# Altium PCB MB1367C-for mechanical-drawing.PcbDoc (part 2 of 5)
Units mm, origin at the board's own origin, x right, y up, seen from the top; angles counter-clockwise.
Board outline 70 x 82.5 mm, 4 copper layers (Top Layer, Signal Layer 1, Signal Layer 2, Bottom Layer), stack 1.614 mm thick; 191 components, 143 nets, 808 pads, 920 vias.
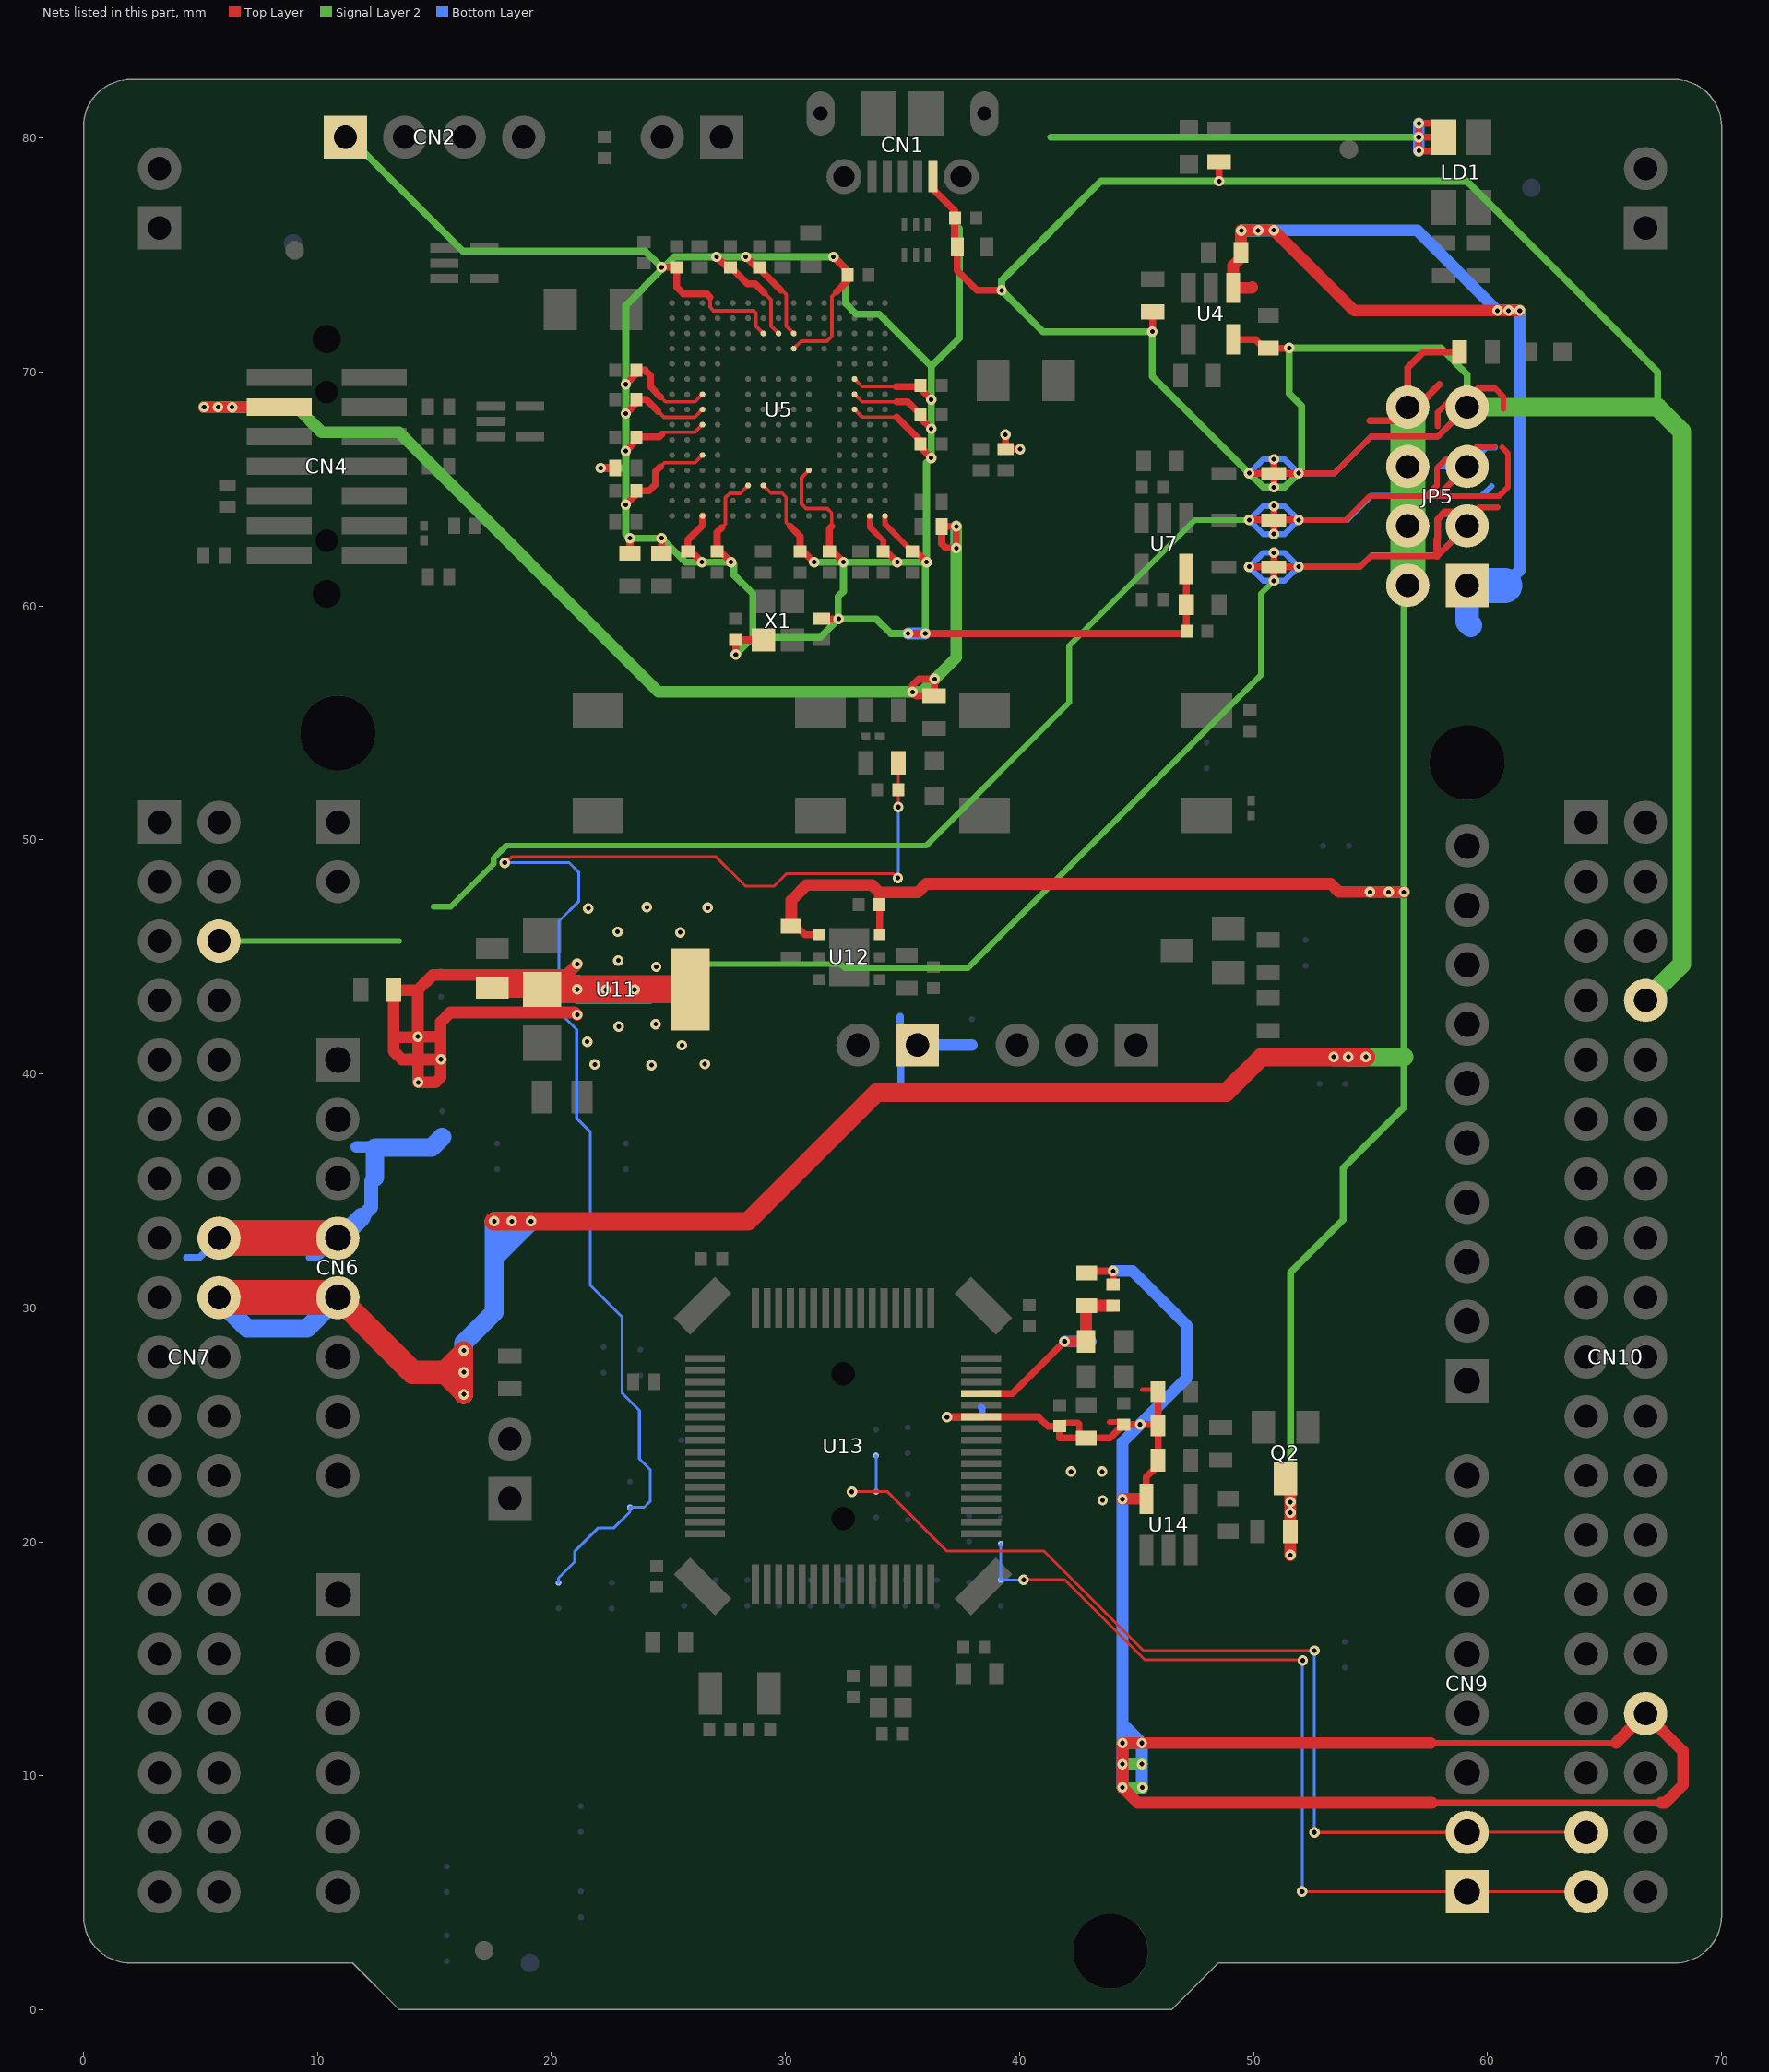
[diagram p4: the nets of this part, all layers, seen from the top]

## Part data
B1: library part MCD-00002, "Non-Open Push-Button 0.1A 24V", Manufacturer=WEALTHMETAL, Manufacturer_Part_Number=TD0341X-G01-BLU
B2: library part MCD-00001, "Non-Open Push-Button 0.1A 24V", Manufacturer=WEALTHMETAL, Manufacturer_Part_Number=TD0341X-G01-BLA
C1 C6 C7 C8 C9 C13 C14 C15 C16 C17 C18 C20 C21 C22 C23 C24 C25 C26 C27 C32 C33 C34 C35 C36 C40 C42 C44 C45 C47 C49 C52 C54: library part MCD-00102, "Capacitor, MLCC, 100nF, 16V, X7R, 10%, 0402, T=0,5mm", Manufacturer=YAGEO, Manufacturer_Part_Number=CC0402KRX7R7BB104, Package=C0402
C2: library part MCD-00205, "Capacitor, MLCC, 100pF, 50V, NPO, 5%, 0402, T=0,5mm", Manufacturer=YAGEO, Manufacturer_Part_Number=CC0402JRNPO9BN101, Package=C0402
C3: library part MCD-00016, "Capacitor, MLCC, 20pF, 50V, NPO, 5%, 0402, T=0,5mm", Manufacturer=YAGEO, Manufacturer_Part_Number=CC0402JRNPO9BN200, Package=C0402
C4: library part MCD-00012, "Capacitor, MLCC, 2.2uF, 10V, X5R, 10%, 0603, T=0,8mm", Alternate_Manufacturer=KEMET, Alternate_Manufacturer_Part_Number=C0603C225K8PACTU, Manufacturer=YAGEO, Manufacturer_Part_Number=CC0603KRX5R6BB225, Package=C0603
C5 C11 C19 C29 C31 C37 C39 C43 C48 C53: library part MCD-00010, "Capacitor, MLCC, 1uF, 16V, X5R, 10%, 0603, T=0,8mm", Manufacturer=YAGEO, Manufacturer_Part_Number=CC0603KRX5R7BB105, Package=C0603
C10 C12: library part MCD-00008, "Capacitor, MLCC, 2.2uF, 16V, X7R, 10%, 1206, T=1,15mm", Alternate_Manufacturer=KEMET, Alternate_Manufacturer_Part_Number=C1206C225K4RAC, Manufacturer=YAGEO, Manufacturer_Part_Number=CC1206KKX7R7BB225, Package=C1206
C28 C55: library part MCD-00009, "Capacitor, MLCC, 4.7uF, 16V, X5R, 10%, 0603, T=0.8mm", Manufacturer=YAGEO, Manufacturer_Part_Number=CC0603KRX5R7BB475, Package=C0603
C30: library part MCD-00011, "Capacitor, MLCC, 10nF, 16V, X7R, 10%, 0402, T=0.5mm", Manufacturer=YAGEO, Manufacturer_Part_Number=CC0402KRX7R7BB103, Package=C0402
C38 C41: library part MCD-00014, "Capacitor, MLCC, 10uF, 25V, X5R, 10%, 0805, T=0,85mm", Manufacturer=YAGEO, Manufacturer_Part_Number=CC0805KRX5R8BB106, Package=C0805
C46: library part MCD-01124, "Capacitor, MLCC, 10µF, 10V, X5R, 10%, 0603, T=0.8mm", Manufacturer=MURATA, Manufacturer_Part_Number=GRM188R61A106KAAL, Package=C0603
C50: library part MCD-00211, "Capacitor, MLCC, 100nF, 16V, X7R, 10%, 0603, T=0,8mm", Manufacturer=YAGEO, Manufacturer_Part_Number=CC0603KRX7R7BB104, Package=C0603
C51: library part MCD-01101, "Capacitor,100pF,50V,X7R,10%,0603", Manufacturer=AVX, Manufacturer_Part_Number=06035C101JAT4A, Package=C0603
C56 C59: library part MCD-00674, "Capacitor, MLCC, 6.8pF, 50V, NPO, +-0.25pF, 0402, T=0.5mm", Manufacturer=YAGEO, Manufacturer_Part_Number=CC0402CRNPO9BN6R8, Package=C0402
C57 C58: library part MCD-00003, "Capacitor, MLCC, 5.1pF, 50V, NPO, +-0.25pF, 0402, T=0.5mm", Manufacturer=YAGEO, Manufacturer_Part_Number=CC0402CRNPO9BN5R1, Package=C0402
CN1: library part MCD-00028, "USB-MICRO-B, 0.65mm, RA, SMT, Bottom Mount,", Manufacturer=MOLEX, Manufacturer_Part_Number=1050170001
CN2: library part MCD-00029, "Header, 4x1, 2,54mm, VR, TH, Height 5.84mm/2.54mm", Manufacturer=SAMTEC, Manufacturer_Part_Number=TSW-104-07-x-S
CN4: library part MCD-00592, "Header 7x2, 1.27mm, Dual row, Straight, \"STDC14_MEDIUM\" : footprint compatible with FTSH-107-01-L-DV,-K,-A,-P,-ES (use \"STDC14_BIG\" to also be compatible with SHF-107-01-L-D-SM,-K)", Manufacturer=SAMTEC, Manufacturer_Part_Number=FTSH-107-01-L-DV-K
CN5: library part MCD-00262, "Socket, 10x1, 2.54mm, VR, TH, Height 8.51mm/10mm", Manufacturer=SAMTEC, Manufacturer_Part_Number=SSW-110-03-x-S
CN6 CN9: library part MCD-00261, "Socket, 8x1, 2.54mm, VR, TH, Height 8.51mm/10mm", Manufacturer=SAMTEC, Manufacturer_Part_Number=SSW-108-03-x-S
CN7 CN10: library part MCD-00213, "Header, 19x2, 2,54mm, VR, TH, Height 5.84mm/10.16mm", Manufacturer=SAMTEC, Manufacturer_Part_Number=TSW-119-09-x-D
CN8: library part MCD-00260, "Socket, 6x1, 2.54mm, VR, TH, Height 8.51mm/10mm", Manufacturer=SAMTEC, Manufacturer_Part_Number=SSW-106-03-x-S
CN11 CN12: library part MCD-00214, "Header, 2x1, 2,54mm, VR, TH, Height 5.84mm/10.16mm", Manufacturer=SAMTEC, Manufacturer_Part_Number=TSW-102-09-x-S
D1 D2 D3: library part MCD-00034, "BAT60JFILM", Manufacturer=STMICROELECTRONICS
HW104: library part MCD-00626, "\"CE\" logo footprint for PCB"
HW106: library part MCD-00625, "\"STMicroelectronics\" logo footprint for PCB", Manufacturer=n/a
HW107: library part MCD-00627, "\"Hand\" ESD logo footprint for PCB", Manufacturer=n/a
JP1 JP7: library part MCD-00045, "Header, 2x1, 2,54mm, VR, TH, Height 5.84mm/2.54mm", Manufacturer=SAMTEC, Manufacturer_Part_Number=TSW-102-07-x-S
JP3 JP6: library part MCD-00683, "Header, 2x1, 2,54mm, VR, TH, Height 5.84mm/2.54mm - Shunt Fitted by default", Manufacturer=SAMTEC, Manufacturer_Part_Number=TSW-102-07-x-S
JP5: library part MCD-00686, "Header, 4x2, 2,54mm, VR, TH, Height 5.84mm/2.54mm - Shunt Fitted 1-2", Manufacturer=SAMTEC, Manufacturer_Part_Number=TSW-104-07-x-D
JP8: library part MCD-00684, "Header, 3x1, 2,54mm, VR, TH, Height 5.84mm/2.54mm - Shunt Fitted 1-2 by default", Manufacturer=SAMTEC, Manufacturer_Part_Number=TSW-103-07-F-S
L1 L2: library part MCD-00047, "SMD Chip ferrite bead, 600R@100MHz +/-25%, 350mA, 500mohm DC, 0603, T=0.8mm", Manufacturer=TAI-TECH, Manufacturer_Part_Number=FCM1608KF-601T03
LD1: library part MCD-00051, "LED Bicolor", Alternate_Manufacturer=EVERLUCK, Alternate_Manufacturer_Part_Number=LE-RGW35280, Manufacturer="AVAGO TECHNOLOGIES", Manufacturer_Part_Number=HSMF-A201-A00J1
LD2 LD3: library part MCD-00050, "LED, Green, 0603", Manufacturer=EVERLIGHT, Manufacturer_Part_Number=19-213SYGC/S530-E2/TR8, Package="LED 0603"
LD4: library part MCD-00049, "LED, Red, 0603", Manufacturer=EVERLIGHT, Manufacturer_Part_Number=19-213-R6C-AP1Q2B/3T, Package="LED 0603"
Q1 Q2: library part MCD-00073, "NPN Bipolar Transistor", Manufacturer=NXP, Manufacturer_Part_Number=BSR14
R1 R30: library part MCD-00070, "Resistor,1K,0603,1%,1/10W", Manufacturer=YAGEO, Manufacturer_Part_Number=RC0603FR-071KL, Package=R0603
R2 R3 R27: library part MCD-00197, "Resistor,330R,0603,1%,1/10W", Manufacturer=YAGEO, Manufacturer_Part_Number=RC0603FR-07330RL, Package=R0603
R4 R15 R20: library part MCD-00119, "Resistor,100R,0402,1%,1/16W", Manufacturer=YAGEO, Manufacturer_Part_Number=RC0402FR-07100RL, Package=R0402
R5: library part MCD-00185, "Resistor,3K,0402,1%,1/16W", Manufacturer=YAGEO, Manufacturer_Part_Number=RC0402FR-073KL, Package=R0402
R6 R26 R28: library part MCD-00223, "Resistor,100K,0603,1%,1/10W", Manufacturer=YAGEO, Manufacturer_Part_Number=RC0603FR-07100KL, Package=R0603
R7 R25: library part MCD-00225, "Resistor,510R,0603,1%,1/10W", Manufacturer=YAGEO, Manufacturer_Part_Number=RC0603FR-07510RL, Package=R0603
R8 R31: library part MCD-00220, "Resistor,10K,0603,1%,1/10W", Manufacturer=YAGEO, Manufacturer_Part_Number=RC0603FR-0710KL, Package=R0603
R9 R10 R13 R18 R22 R23 R32: library part MCD-00189, "Resistor,22R,0402,1%,1/16W", Manufacturer=YAGEO, Manufacturer_Part_Number=RC0402FR-0722RL, Package=R0402
R11 R16 R19: library part MCD-00065, "Resistor,4K7,0402,1%,1/16W", Alternate_Manufacturer=YAGEO, Alternate_Manufacturer_Part_Number=RT0402FRE074K7L, Manufacturer_Part_Number=RC0402FR-074K7L, Package=R0402
R12: library part MCD-00055, "Resistor,2K7,0402,1%,1/16W", Manufacturer=YAGEO, Manufacturer_Part_Number=RC0402FR-072K7L, Package=R0402
R14 R17 R21 R24: library part MCD-00053, "Resistor,10K,0402,1%,1/16W", Manufacturer=YAGEO, Manufacturer_Part_Number=RC0402FR-0710KL, Package=R0402
R29: library part MCD-00222, "Resistor,47K,0603,1%,1/10W", Manufacturer=YAGEO, Manufacturer_Part_Number=RC0603FR-0747KL, Package=R0603
R33: library part MCD-01215, "resistor, 10K, 0603, 0.5%, 1/10W", Manufacturer=YAGEO, Manufacturer_Part_Number=RC0603DR-0710KL, Package=R0603
R34: library part MCD-01209, "Resistor,33K,0603,0.5%,1/10W", Manufacturer=YAGEO, Manufacturer_Part_Number=RC0603DR-0733KL, Package=R0603
R35: library part MCD-00528, "Resistor,820R,0603,1%,1/10W", Manufacturer=YAGEO, Manufacturer_Part_Number=RC0603FR-07820RL, Package=R0603
SB1 SB2 SB3 SB4 SB5 SB6 SB7 SB8 SB9 SB10 SB11 SB12 SB13 SB14 SB15 SB16 SB17 SB18 SB19 SB20 SB21 SB22 SB23 SB24 SB25 SB26 SB27 SB28 SB29 SB30 SB31 SB32 SB33 SB34 SB35 SB36 SB37 SB38 SB39 SB40 SB41: library part MCD-00071, "Solder Bridge ON"
U1 U6: library part MCD-00136, "Dual Transil array for ESD protection", Manufacturer=STMICROELECTRONICS, Manufacturer_Part_Number=ESDALC6V1W5
U2: library part MCD-00649, "Common mode filter with ESD protection for USB 2.0 interface", Manufacturer=STMICROELECTRONICS, Manufacturer_Part_Number=ECMF02-2AMX6
U3: library part MCD-00251, "High power transient voltage suppressor, 7V breakdown", Manufacturer=STMICROELECTRONICS, Manufacturer_Part_Number=ESDA7P60-1U1M
U4: library part MCD-00159, "500mA, Enhanced single channel power switches with active high enable pin", Alternate_Manufacturer="TEXAS INSTRUMENTS", Alternate_Manufacturer_Part_Number=TPS2051C, Manufacturer=STMICROELECTRONICS, Manufacturer_Part_Number=STMPS2151STR
U5: library part MCD-00596, "STM32F723IEK  (STM32F7) BGA176", Manufacturer=STMICROELECTRONICS, Manufacturer_Part_Number=STM32F723IEK6
U7: library part MCD-00086, "Ultra low drop-low noise BiCMOS voltage, regulators low ESR capacitors compatible", Manufacturer=STMICROELECTRONICS, Manufacturer_Part_Number=LD3985M33R
U8 U9 U10: library part MCD-00170, "ESD protection 6V1", Manufacturer=STMICROELECTRONICS, Manufacturer_Part_Number=ESDALC6V1-1U2
U11: library part MCD-00088, "IC REG LDO 5V 0.8A SOT223", Manufacturer=STMICROELECTRONICS, Manufacturer_Part_Number=LD1117S50TR
U12: library part MCD-00215, "Low quiescent current and low noise voltage regulators", Manufacturer=STMICROELECTRONICS, Manufacturer_Part_Number=LD39050PU33R
U13: library part MCD-01243, "STM32G474, LQFP64 package,  3D IC footprint with 2D socket footprint.", Manufacturer=STMICROELECTRONICS, Manufacturer_Part_Number=STM32G474RET6, Package=LQFP64
U14: library part MCD-01157, "Programmable voltage reference", Manufacturer=STMICROELECTRONICS, Manufacturer_Part_Number=TL1431ACL5T, Package=SOT23-5L
X1: library part MCD-00597, "Oscillator 25.00Mhz, -+50PPM, 3.3V, Temp -55 to +125°C", Alternate_Manufacturer="AVX CORP/KYOCERA CORP", Alternate_Manufacturer_Part_Number=KC2520B25.0000C10E00, Manufacturer=NDK, Manufacturer_Part_Number="NZ2520SB 25MHz END4869B"
X2: library part MCD-00091, "Crystal 32.768kHz, 6pF, -+20PPM, R=50K, SMD", Manufacturer=NDK, Manufacturer_Part_Number="NX3215SA 32.768KHz EXS00A-MU00525"
X3: library part MCD-01036, "24MHz crystal oscillator - Cl:6pf -", Manufacturer=NDK, Manufacturer_Part_Number="NX2016SA 24MHz EXS00A-CS10820", Package="(2016) 2.0 x 1.6 x 0.45 mm"

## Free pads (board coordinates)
  round 3.2 hole 3.2 unplated: 0(10.87,54.57) 0(43.89,2.5) 0(59.13,53.3)

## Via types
v1: diameter 0.45, hole 0.2, Top Layer to Bottom Layer, tented both sides, 920 vias

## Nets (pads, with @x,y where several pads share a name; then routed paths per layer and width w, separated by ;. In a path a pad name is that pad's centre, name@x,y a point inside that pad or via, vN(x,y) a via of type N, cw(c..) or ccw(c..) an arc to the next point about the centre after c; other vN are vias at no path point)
3V3: CN4.3 CN6.4 CN7.16 JP6.1 R19.2 R25.1 SB5.2 SB39.1 | length 88.7
  Top Layer w0.3: v1(6.35,68.495) v1@6.36,68.505 ; v1(35.425,56.325) 35.585,56.165 R25.1@36.345,56.165 36.375,56.195 v1(36.375,56.875) 35.7,56.875 35.425,56.6 v1(35.425,56.325) ; 36.675,62.65 R19.2@36.675,63.4 v1(37.3,63.4) v1(37.3,62.475) 36.85,62.475 36.675,62.65
  Top Layer w0.5: v1(5.15,68.5) v1(5.75,68.5) 5.755,68.495 v1(6.35,68.495) ; v1@6.36,68.505 CN4.3@8.363,68.505
  Top Layer w1.5: CN7.16@5.79,32.98 CN6.4@10.87,32.98
  Signal Layer 2 w0.5: v1(5.15,68.5) v1(5.75,68.5) 6.345,68.5 v1(6.35,68.495) 9.105,68.495 10.175,67.425 13.475,67.425 24.575,56.325 v1(35.425,56.325) 35.825,56.325 v1(36.375,56.875) 37.3,57.8 v1(37.3,62.475) v1(37.3,63.4)
  Signal Layer 2 w1.5: CN7.16@5.79,32.98 CN6.4@10.87,32.98
  Bottom Layer w0.3: 4.4,32.15 4.96,32.15 CN7.16@5.79,32.98 ; 9.65,32.15 10.04,32.15 CN6.4@10.87,32.98 ; 34.9,42.45 34.9,41.97 JP6.1@35.635,41.235 34.925,40.525 34.925,39.625
  Bottom Layer w0.5: v1(5.15,68.5) v1(5.75,68.5) 5.753,68.498 6.347,68.498 v1(6.35,68.495) ; 11.65,36.875 12.425,36.875 12.45,36.85 ; v1(35.425,56.325) 35.825,56.325 v1(36.375,56.875) ; JP6.1@35.635,41.235 37.965,41.235 SB5.2@37.97,41.24 ; v1(37.3,62.475) v1(37.3,63.4)
  Bottom Layer w0.6: 11.875,33.875 12.3,34.3 12.3,35.425 12.45,35.575
  Bottom Layer w0.8: CN7.16@5.79,32.98 CN6.4@10.87,32.98 10.98,32.98 11.875,33.875 ; 12.45,35.575 12.45,36.85 14.3,36.85 14.875,36.85 SB39.1@15.325,37.3
3V3_STLK: C6.2 C7.2 C8.2 C9.2 C13.2 C14.2 C15.2 C16.2 C17.2 C18.2 C21.2 C22.2 C23.2 C24.2 C25.2 C26.2 C27.2 C28.2 C29.2 C31.2 C32.2 C33.2 CN2.1 LD1.4 R14.1 R24.1 U5.C1 U5.C5 U5.C7 U5.C8 U5.C9 U5.F3 U5.G3 U5.G13 U5.H13 U5.J12 U5.J13 U5.K4 U5.N8 U5.N9 U5.N10 U5.P1 U5.R1 U7.5 X1.4 | length 200.2
  Top Layer w0.15: 24.55,68.325 24.805,68.07 26.12,68.07 U5.C8@26.45,68.4 ; 24.65,65.95 24.825,66.125 26.125,66.125 U5.C5@26.45,66.45 ; 24.65,68.95 24.875,68.725 26.125,68.725 U5.C9@26.45,69.05 ; 24.725,67.35 24.805,67.43 26.13,67.43 U5.C7@26.45,67.75 ; 27.275,63.35 27.43,63.505 27.43,64.633 27.617,64.82 28.07,64.82 U5.F3@28.4,65.15 ; U5.G3@29.05,65.15 29.37,64.83 29.845,64.83 30.025,64.65 30.025,63.575 30.2,63.4 ; U5.J12@30.35,71 30.67,71.32 31.773,71.32 31.98,71.527 31.98,73.23 32.175,73.425 ; U5.K4@31,65.8 30.68,65.48 30.68,64.367 30.877,64.17 31.783,64.17 31.975,63.978 31.975,63.4 ; U5.N8@32.95,68.4 33.27,68.08 34.745,68.08 ; U5.N9@32.95,69.05 33.275,68.725 34.75,68.725 ; U5.N10@32.95,69.7 33.275,69.375 34.725,69.375
  Top Layer w0.16: 26.775,73.2 26.775,73.085 26.775,72.775 26.925,72.625 28.5,72.625 ; 28.535,72.625 28.625,72.625 28.725,72.525 28.725,72.165 28.725,71.975 U5.G13@29.05,71.65 ; 29.1,73.375 29.375,73.1 29.375,71.975 U5.H13@29.7,71.65 ; 29.825,73.5 30.025,73.3 30.025,71.975 U5.J13@30.35,71.65
  Top Layer w0.25: U5.P1@33.6,63.85 33.6,63.375 34.175,62.8 C26.2@34.175,62.325 ; U5.R1@34.25,63.85 34.25,63.5 C27.2@35.425,62.325
  Top Layer w0.3: v1(22.1,65.9) R14.1@22.725,65.9 ; v1(23.175,64.325) 23.625,64.775 C21.2@23.625,64.925 24.175,64.925 24.45,65.2 24.45,65.75 24.65,65.95 ; v1(23.175,66.625) 23.625,67.075 C17.2@23.625,67.225 24.6,67.225 24.725,67.35 ; v1(23.175,68.225) 23.625,68.675 C15.2@23.625,68.825 24.05,68.825 24.55,68.325 ; v1(23.175,69.475) C13.2@23.625,69.925 ; C28.2@23.35,62.25 v1(23.35,62.9) ; C13.2@23.675,69.925 C13.2@23.625,69.925 ; 24.65,68.95 24.225,69.375 24.225,69.85 24,70.075 C13.2@23.625,70.075 C13.2@23.625,69.925 ; C29.2@24.7,62.25 v1(24.7,62.9) ; v1(24.7,74.475) C6.2@25.35,74.475 25.35,73.625 25.625,73.35 26.625,73.35 26.775,73.2 ; v1(26.425,61.875) 25.975,62.325 C22.2@25.825,62.325 25.825,62.825 26.45,63.45 U5.C1@26.45,63.85 ; v1(27.05,74.925) 27.5,74.475 C7.2@27.65,74.475 ; 27.275,63.35 27.075,63.15 C23.2@27.075,62.325 27.225,62.325 v1(27.675,61.875) ; C7.2@27.65,74.45 27.7,74.45 28.375,73.775 28.7,73.775 29.1,73.375 ; v1(27.875,57.925) C32.2@27.875,58.55 X1.4@29.05,58.55 ; v1(28.3,74.925) 28.75,74.475 C8.2@28.9,74.475 28.9,74.4 29.8,73.5 ; 30.2,63.4 30.625,62.975 C24.2@30.625,62.325 30.775,62.325 v1(31.225,61.875) ; R24.1@31.55,59.45 v1(32.275,59.45) ; 31.975,63.4 31.875,63.3 C25.2@31.875,62.325 32.025,62.325 v1(32.475,61.875) ; v1(32.05,74.925) 32.65,74.325 C9.2@32.65,74.15 32.65,73.9 32.175,73.425 ; C26.2@34.175,62.325 34.325,62.325 v1(34.775,61.875) ; 34.725,69.375 35.725,69.375 C14.2@35.775,69.425 35.775,69.275 v1(36.225,68.825) ; 34.745,68.08 35.775,67.05 C18.2@35.775,66.925 35.775,66.775 v1(36.225,66.325) ; 34.75,68.725 35.225,68.725 C16.2@35.775,68.175 35.775,68.025 v1(36.225,67.575) ; v1(35.238,58.825) v1(35.975,58.825) 47.23,58.825 C33.2@47.13,58.925 C31.2@47.13,60.05 U7.5@47.13,61.575 ; C27.2@35.425,62.325 35.575,62.325 v1(36.025,61.875) ; v1(57.06,80.04) v1@57.065,80.04 ; LD1.4@58.12,80.04 v1@57.065,80.04 ; LD1.4@58.125,79.45 v1(57.065,79.45) v1@57.065,80.04 ; LD1.4@58.125,80.625 v1(57.065,80.625) v1@57.065,80.04
  Signal Layer 2 w0.3: CN2.1@11.19,80.04 11.335,80.04 16.2,75.175 24,75.175 v1(24.7,74.475) v1@24.7,74.375 ; v1(22.1,65.9) 23.15,65.9 23.175,65.875 ; v1(27.875,57.925) 28.6,58.65 ; v1(31.225,61.875) v1(32.475,61.875) ; 37.425,76.125 37.425,71.45 36.225,70.25 ; 41.34,80.04 v1(57.06,80.04) ; 23.175,65.875 v1(23.175,64.325) 23.175,63.075 v1(23.35,62.9) v1(24.7,62.9) 25.725,61.875 v1(26.425,61.875) v1(27.675,61.875) 27.785,61.765 27.785,61.335 28.6,60.52 28.6,58.65 ; 23.175,65.875 v1(23.175,66.625) v1(23.175,68.225) v1(23.175,69.475) 23.175,72.85 v1@24.7,74.375 ; v1@24.7,74.375 25.25,74.925 v1(27.05,74.925) v1(28.3,74.925) v1(32.05,74.925) 32.575,74.4 32.575,72.925 33.025,72.475 34,72.475 36.225,70.25 ; 28.6,58.65 31.475,58.65 v1(32.275,59.45) ; v1(32.275,59.45) 32.255,59.47 32.255,60.405 32.475,60.625 v1(32.475,61.875) ; v1(32.275,59.45) 33.875,59.45 34.5,58.825 v1(35.238,58.825) v1(35.975,58.825) 35.975,61.825 v1(36.025,61.875) ; v1(32.475,61.875) v1(34.775,61.875) v1(36.025,61.875) ; v1(36.025,61.875) 36.025,66.125 v1(36.225,66.325) v1(36.225,67.575) v1(36.225,68.825) 36.225,70.25
  Bottom Layer w0.5: v1(35.238,58.825) v1(35.975,58.825) ; v1(57.065,79.45) v1(57.065,80.625)
5V: C36.2 C37.2 CN6.5 CN7.18 JP5.2 JP5.4 JP5.6 JP5.8 Q2.3 R7.2 R12.1 R35.2 U12.1 U12.6 | length 186.8
  Top Layer w0.3: C37.2@30.245,46.315 30.46,46.315 30.835,45.94 U12.1@31.42,45.94 ; U12.6@34.02,45.94 C36.2@34.02,47.24 ; v1(39.4,67.325) R12.1@39.4,66.7 v1(40.025,66.7) ; Q2.3@51.37,22.69 Q2.3@51.57,22.49 ; v1@51.57,19.43 v1(51.575,19.435) ; 54.975,67.925 56.015,67.925 JP5.8@56.59,68.5 ; 57.95,69.475 56.975,68.5 JP5.8@56.59,68.5 ; R7.2@58.8,70.85 57.25,70.85 56.59,70.19 JP5.8@56.59,68.5
  Top Layer w0.5: C37.2@30.245,46.315 30.245,47.42 30.9,48.075 33.7,48.075 34.02,47.755 ; C36.2@34.02,47.24 34.02,47.755 ; v1@51.57,19.43 R35.2@51.57,20.44 Q2.3@51.57,22.49 ; v1(56.425,47.775) 56.425,47.75 56.4,47.775 v1(55.775,47.775) v1(54.975,47.775) 53.65,47.775 53.3,48.125 36.015,48.125 35.645,47.755 34.02,47.755
  Top Layer w0.8: v1(16.25,26.3) v1@16.25,26.325 ; v1(17.55,33.7) v1(18.3,33.7) v1(19.125,33.7) 28.4,33.7 33.9,39.2 48.825,39.2 50.35,40.725 v1(53.425,40.725) v1(54.05,40.725) v1(54.8,40.725) ; 15.325,27.25 v1(16.25,28.175) v1(16.25,27.25) ; 15.325,27.25 v1(16.25,27.25) ; 15.325,27.25 v1@16.25,26.325 ; v1@16.25,26.325 v1(16.25,27.25)
  Top Layer w1: CN6.5@10.87,30.44 14.06,27.25 15.325,27.25
  Top Layer w1.5: CN7.18@5.79,30.44 CN6.5@10.87,30.44
  Signal Layer 2 w0.3: v1(51.575,19.435) v1(51.575,21.25) v1(51.575,21.7) 51.575,31.525 53.825,33.775 53.825,35.975 56.425,38.575 56.425,40.725 v1(56.425,47.775) 56.425,60.715 JP5.2@56.59,60.88
  Signal Layer 2 w0.5: v1(55.775,47.775) v1(56.425,47.775)
  Signal Layer 2 w0.8: v1(16.25,26.3) v1(16.25,27.25) v1(16.25,28.175) ; v1(17.55,33.7) v1(18.3,33.7) v1(19.125,33.7) ; v1(54.05,40.725) v1(54.8,40.725) 56.425,40.725
  Signal Layer 2 w1.5: CN7.18@5.79,30.44 CN6.5@10.87,30.44 ; JP5.2@56.59,60.88 JP5.4@56.59,63.42 JP5.6@56.59,65.96 JP5.8@56.59,68.5
  Bottom Layer w0.3: v1(51.575,19.435) v1(51.575,21.25) v1@51.575,21.675
  Bottom Layer w0.5: v1(54.975,47.775) v1(55.775,47.775) v1(56.425,47.775)
  Bottom Layer w0.8: CN7.18@5.79,30.44 5.79,30.335 7,29.125 9.555,29.125 CN6.5@10.87,30.44 ; v1(16.25,26.3) v1(16.25,27.25) v1(16.25,28.175) 16.25,28.5 17.55,29.8 17.55,32.125 ; v1(53.425,40.725) v1(54.05,40.725) v1(54.8,40.725) ; 17.55,32.125 17.55,32.95 ; 17.55,32.125 v1(19.125,33.7) v1(18.3,33.7) ; 17.55,32.95 v1(17.55,33.7) v1(18.3,33.7) ; 17.55,32.95 v1(18.3,33.7)
5V_USB_CHGR: C2.2 C11.2 CN1.1 CN10.8 D1.1 JP5.7 R1.2 R6.2 U3.1 U4.5 | length 143.8
  Top Layer w0.25: v1(51.925,65.675) 53.45,65.675 55.025,67.25 57.88,67.25 JP5.7@59.13,68.5 ; 57.875,67.675 57.875,68.275 58.475,68.875 58.755,68.875 JP5.7@59.13,68.5 ; 60.675,68.425 60.675,68.95 60.325,69.3 59.575,69.3 59.13,68.855 JP5.7@59.13,68.5
  Top Layer w0.3: CN1.1@36.3,78.35 36.3,77.82 37.18,76.94 ; v1(39.235,73.49) 39.235,73.553 39.172,73.49 38.185,73.49 37.33,74.345 37.33,75.64 37.215,75.64 37.225,75.65 C2.2@37.225,76.845 ; v1(45.675,71.725) 45.685,71.735 R6.2@45.685,72.57 ; v1(48.533,78.158) R1.2@48.533,78.98 ; U4.5@49.125,71.395 50.08,71.395 50.455,71.02 C11.2@50.635,71.02 51.52,71.02 v1(51.525,71.025) ; v1(49.815,65.675) D1.1@50.87,65.675 ; v1(50.87,65.075) D1.1@50.87,65.675 ; v1(50.87,66.275) D1.1@50.87,65.675 ; v1(51.925,65.675) D1.1@50.87,65.675 ; 37.18,76.94 37.18,76.89 C2.2@37.225,76.845 ; 37.18,76.94 37.225,76.895 C2.2@37.225,76.845
  Signal Layer 2 w0.3: JP5.7@59.13,68.5 59.13,69.895 58,71.025 v1(51.525,71.025) 51.525,69.075 52.05,68.55 52.05,65.8 v1(51.925,65.675) 51.325,65.075 v1(50.87,65.075) 50.415,65.075 v1(49.815,65.675) 45.675,69.815 v1(45.675,71.725) 41,71.725 v1(39.235,73.49) 39.235,73.91 43.483,78.158 v1(48.533,78.158) 59.117,78.158 67.275,70 67.275,68.5
  Signal Layer 2 w0.8: JP5.7@59.13,68.5 67.275,68.5 68.3,67.475 68.3,44.69 CN10.8@66.75,43.14
  Bottom Layer w0.25: JP5.7@59.13,68.5 57.88,67.25 55.025,67.25 53.45,65.675 v1(51.925,65.675) ; v1(51.925,65.675) 51.325,66.275 v1(50.87,66.275) 50.415,66.275 v1(49.815,65.675) 50.415,65.075 v1(50.87,65.075) 51.325,65.075 v1(51.925,65.675)
5V_USB_STLK: C5.2 JP5.1 U4.1 | length 47.8
  Top Layer w0.3: C5.2@49.46,74.885 C5.2@49.46,75.12
  Top Layer w0.5: C5.2@49.46,74.885 49.125,74.55 U4.1@49.125,73.595 49.92,73.595 49.95,73.625 ; C5.2@49.46,75.12 49.46,76.06 v1(50.865,76.06) 54.3,72.625 v1(60.425,72.625) v1(60.9,72.625) v1(61.375,72.625)
  Signal Layer 2 w0.5: v1(49.475,76.045) 49.48,76.05 v1(50.2,76.05) 50.21,76.06 v1(50.865,76.06) ; v1(60.425,72.625) v1(60.9,72.625) v1(61.375,72.625)
  Bottom Layer w0.5: v1(49.475,76.045) 50.195,76.045 v1(50.2,76.05) 50.855,76.05 v1(50.865,76.06) 56.99,76.06 v1(60.425,72.625) v1(60.9,72.625) v1(61.375,72.625) 61.375,61.525 60.73,60.88
  Bottom Layer w1: JP5.1@59.13,60.88 59.13,59.32 59.275,59.175
  Bottom Layer w1.5: JP5.1@59.13,60.88 60.73,60.88
5V_VIN: C38.2 D3.1 JP5.3 R30.2 U11.2 U11.4 | length 107.8
  Top Layer w0.25: v1(51.925,61.675) 54.55,61.675 55.005,62.13 57.84,62.13 JP5.3@59.13,63.42 59.13,63.73 59.616,64.216 60.416,64.216 60.425,64.225
  Top Layer w0.3: v1(49.815,61.675) D3.1@50.87,61.675 ; v1(50.87,61.075) D3.1@50.87,61.675 ; v1(50.87,62.275) D3.1@50.87,61.675 ; v1(51.925,61.675) D3.1@50.87,61.675 ; 57.84,62.13 57.84,62.842 57.865,62.867 57.865,63.703 58.17,64.008 58.542,64.008 JP5.3@59.13,63.42
  Top Layer w0.5: v1(15.275,40.625) v1@15.265,40.615 ; v1(21.1,42.525) 21,42.625 15.675,42.625 15.265,42.215 15.265,41.575 ; v1(21.1,44.7) 20.625,44.225 14.925,44.225 14.285,43.585 ; 13.25,41.575 14.265,41.575 v1(14.285,41.595) ; 13.25,41.575 13.25,40.975 13.61,40.615 14.295,40.615 ; 13.25,41.575 R30.2@13.25,43.575 14.275,43.575 14.285,43.585 ; v1(14.285,41.595) 14.295,41.585 14.295,40.615 ; v1(14.285,41.595) 15.245,41.595 15.265,41.575 ; v1(14.285,41.595) 14.285,43.585 ; 14.295,40.615 v1@15.265,40.615 ; 14.295,40.615 14.295,39.645 v1(14.305,39.635) 15.035,39.635 15.265,39.865 v1@15.265,40.615 ; v1@15.265,40.615 15.265,41.575
  Top Layer w0.8: C38.2@17.47,43.665 19.545,43.665 U11.2@19.595,43.615
  Top Layer w1.2: U11.2@19.595,43.615 v1(21.1,43.615) U11.4@25.945,43.615
  Signal Layer 2 w0.25: 26.3,44.55 26.445,44.695 32.35,44.695 32.525,44.52 37.795,44.52 50.325,57.05 50.325,60.53 v1(50.87,61.075)
  Signal Layer 2 w1.2: v1(21.1,43.615) 21.115,43.6 v1(22.325,43.6) v1(23.55,43.6) 24.175,43.6
  Bottom Layer w0.25: 57.875,63.713 58.093,63.931 58.619,63.931 JP5.3@59.13,63.42 57.88,62.17 55.045,62.17 54.55,61.675 v1(51.925,61.675) ; v1(51.925,61.675) 51.325,62.275 v1(50.87,62.275) 50.415,62.275 v1(49.815,61.675) 50.415,61.075 v1(50.87,61.075) 51.325,61.075 v1(51.925,61.675)
  Bottom Layer w1.2: v1(21.1,43.615) 21.115,43.6 v1(22.325,43.6) v1(23.55,43.6) 24.175,43.6
  other v1: 24.275,40.375 21.85,40.4 26.55,40.425 25.575,41.225 21.525,41.375 22.875,42.025 24.45,42.125 24.475,44.575 22.85,44.85 25.5,46.05 22.825,46.075 21.575,47.075 26.675,47.1 24.075,47.125
AGND: C43.1 C44.1 C46.1 C47.1 C48.2 C49.2 C50.1 CN10.32 R34.1 SB11.2 U13.27 U14.5 | length 107.7
  Top Layer w0.2: 45.25,26.5 45.835,26.5 C46.1@45.92,26.415
  Top Layer w0.25: C49.2@41.72,24.94 41.88,25.1 42.5,25.1 42.55,25.05 42.55,24.735 C48.2@42.845,24.44 ; 43.85,25.125 44.335,25.125 C47.1@44.445,25.015 ; 57.575,11.4 65.49,11.4 ; 57.625,8.85 67.425,8.85
  Top Layer w0.3: v1(36.9,25.325) 36.915,25.34 40.81,25.34 41.21,24.94 C49.2@41.72,24.94 41.72,24.44 C48.2@42.845,24.44 43.87,24.44 C47.1@44.445,25.015 v1(45.15,25.015) 45.87,25.015 C50.1@45.92,24.965 ; C43.1@42.87,31.49 42.95,31.57 43.995,31.57 C44.1@43.995,30.99 ; U14.5@45.42,21.84 45.42,22.765 45.92,23.265 R34.1@45.92,23.49 C50.1@45.92,24.965 ; C46.1@45.92,26.415 C50.1@45.92,24.965
  Top Layer w0.5: v1(44.4,21.825) 44.415,21.84 U14.5@45.42,21.84 ; 57.575,11.4 v1(45.225,11.4) v1(44.4,11.4) v1(44.4,10.5) v1(44.4,9.5) 45.05,8.85 57.625,8.85 ; 65.49,11.4 CN10.32@66.75,12.66 68.35,11.06 68.35,9.6 67.6,8.85 67.425,8.85
  Signal Layer 2 w0.5: v1(44.4,9.5) v1(45.25,9.5) ; v1(44.4,10.5) v1(45.225,10.5) ; v1(44.4,11.4) v1(45.225,11.4)
  Bottom Layer w0.3: v1(36.9,25.325) 38.4,25.325 38.4,25.7 SB11.2@38.36,25.74
  Bottom Layer w0.5: v1(44,31.575) 44.825,31.575 47.15,29.25 47.15,27.015 v1(45.15,25.015) 44.4,24.265 v1(44.4,21.825) 44.4,12.225 ; v1@45.225,9.45 v1@45.225,9.5 ; v1(45.25,9.5) v1@45.225,9.5 ; v1(44.4,11.4) 44.4,12.225 ; v1(44.4,11.4) v1(45.225,11.4) ; v1(44.4,11.4) v1(44.4,10.5) v1(44.4,9.5) v1@45.225,9.5 ; 44.4,12.225 v1(45.225,11.4) ; v1@45.225,9.5 v1(45.225,10.5) v1(45.225,11.4)
  other v1: 43.55,21.775 42.2,23 43.525,23
ARD_D0_RX: CN9.1 CN10.37 SB19.2 SB22.2 | length 37.9
  Top Layer w0.12: v1(40.175,18.375) 41.936,18.375 45.361,14.95 52.1,14.95 52.1,14.928 v1(52.103,14.926) ; v1(52.075,5.05) 52.085,5.04 CN9.1@59.13,5.04 CN10.37@64.21,5.04
  Bottom Layer w0.12: SB19.2@39.195,19.915 SB22.2@39.195,18.365 40.165,18.365 v1(40.175,18.375) ; v1(52.075,5.05) 52.076,14.926 v1(52.103,14.926)
ARD_D1_TX: CN9.2 CN10.35 SB13.2 SB18.2 | length 44.5
  Top Layer w0.12: v1(32.835,22.14) 34.36,22.14 36.9,19.6 41.05,19.6 45.3,15.35 v1(52.6,15.35) ; v1(52.6,7.575) 59.125,7.575 CN9.2@59.13,7.58 CN10.35@64.21,7.58
  Bottom Layer w0.12: v1(32.835,22.14) SB18.2@33.87,22.14 SB13.2@33.87,23.69 ; v1(52.6,7.575) v1(52.6,15.35)
AVDD: C43.2 C44.2 L1.2 SB8.2 U13.29 | length 9.2
  Top Layer w0.3: U13.29@38.36,26.34 39.7,26.34 v1(41.925,28.565) ; C43.2@42.845,30.065 C43.2@42.87,30.09
  Top Layer w0.45: v1(41.925,28.565) L1.2@42.845,28.565
  Top Layer w0.5: L1.2@42.845,28.565 C43.2@42.845,30.065 ; C43.2@42.87,30.09 C44.2@43.995,30.09
  Bottom Layer w0.5: v1(41.925,28.565) SB8.2@43.045,28.565
B_USER: C35.2 R27.2 SB16.1 SB21.1 | length 60.7
  Top Layer w0.12: v1(18.001,49.027) 18.003,49.025 18.045,49.025 18.3,49.28 27.031,49.28 28.281,48.03 29.517,48.03 30.047,48.56 34.615,48.56 v1(34.8,48.375) ; v1(34.82,51.405) C35.2@34.82,52.14 R27.2@34.82,53.29
  Bottom Layer w0.12: v1(18.001,49.027) 20.749,49.027 21.17,48.606 21.17,47.379 20.32,46.529 20.32,42.65 21.075,41.895 21.075,38.1 21.665,37.51 21.665,30.96 23.025,29.6 23.025,26.35 23.755,25.62 23.755,23.547 24.21,23.092 24.21,21.725 23.96,21.475 SB16.1@23.35,21.475 23.35,21.275 22.675,20.6 22.007,20.6 20.98,19.573 20.98,19.13 20.3,18.45 SB21.1@20.3,18.25 ; v1(34.8,48.375) 34.8,48.45 34.82,48.47 v1(34.82,51.405)
E5V: CN7.6 D2.1 JP5.5 | length 90.6
  Top Layer w0.25: v1(51.925,63.675) 53.95,63.675 54.975,64.7 57.375,64.7 ; 57.825,64.875 57.935,64.765 ; 60.275,66.8 59.525,66.8 59.13,66.405 JP5.5@59.13,65.96 ; 60.625,66.775 60.875,66.525 60.875,65.075 60.5,64.7 58,64.7 57.935,64.765 ; 57.375,64.7 57.84,65.165 57.84,65.89 58.225,66.275 58.815,66.275 JP5.5@59.13,65.96 ; 57.375,64.7 57.87,64.7 57.935,64.765 ; 57.935,64.765 JP5.5@59.13,65.96
  Top Layer w0.3: v1(49.815,63.675) D2.1@50.87,63.675 ; v1(50.87,63.075) D2.1@50.87,63.675 ; v1(50.87,64.275) D2.1@50.87,63.675 ; v1(51.925,63.675) D2.1@50.87,63.675
  Signal Layer 2 w0.25: CN7.6@5.79,45.68 13.49,45.68 ; 14.955,47.145 15.701,47.145 17.531,48.975 17.531,49.222 18.069,49.76 36.01,49.76 42.125,55.875 42.125,58.3 47.5,63.675 v1(49.815,63.675)
  Bottom Layer w0.25: 57.9,65.95 57.91,65.96 JP5.5@59.13,65.96 ; 58.125,64.775 58.2,64.7 59.75,64.7 60.175,65.125 ; 60.325,66.775 59.945,66.775 JP5.5@59.13,65.96 ; v1(51.925,63.675) 54,63.675 55.035,64.71 57.88,64.71 JP5.5@59.13,65.96 ; v1(51.925,63.675) 51.325,64.275 v1(50.87,64.275) 50.415,64.275 v1(49.815,63.675) 50.415,63.075 v1(50.87,63.075) 51.325,63.075 v1(51.925,63.675)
